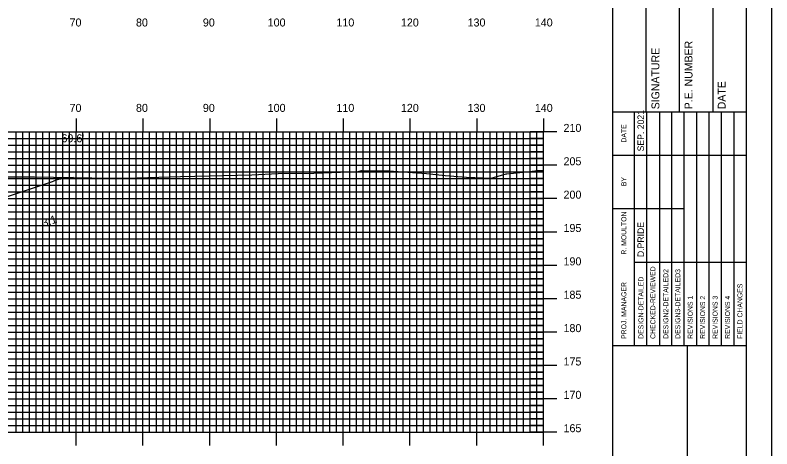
# Model space of a CAD drawing. Extents: x 1795633 to 1795976, y 442591 to 442811.
# Drawn here: x 1795859.7 to 1795973.1, y 442671.2 to 442736.2 of the extents above; entities that cross this region are included whole.
import ezdxf

# ---------------------------------------------------------------- set-up
doc = ezdxf.new("R2010")
doc.units = 0
for name, color, linetype in [('ANNOTATION', 7, 'Continuous'), ('BORDER', 7, 'Continuous'), ('D_Roadway_SlopeLines', 7, 'Continuous'), ('D_Text_Standard', 7, 'Continuous'), ('H_V ANNOTATION', 7, 'Continuous'), ('MAJOR', 7, 'Continuous'), ('MINOR', 7, 'Continuous'), ('PLOT BOUNDARY', 7, 'Continuous'), ('S_Roadway_Centerline', 7, 'Continuous')]:
    doc.layers.add(name, color=color, linetype=linetype)

msp = doc.modelspace()

# ---------------------------------------------------------------- linework, layer by layer
at = {"layer": 'BORDER'}
for p, q in [((1795949.28, 442596.67), (1795949.28, 442806.67)), ((1795954.28, 442721.67), (1795954.28, 442738.97)), ((1795959.28, 442721.67), (1795959.28, 442738.97)), ((1795964.28, 442721.67), (1795964.28, 442738.97)), ((1795949.28, 442721.67), (1795969.28, 442721.67)), ((1795949.28, 442686.67), (1795969.28, 442686.67)), ((1795960.46, 442616.67), (1795960.46, 442686.67))]:
    msp.add_line(p, q, dxfattribs=at)
msp.add_lwpolyline([(1795649.28, 442596.67), (1795969.28, 442596.67), (1795969.28, 442806.67), (1795649.28, 442806.67)], close=True, dxfattribs=at)
for points in [[(1795952.51, 442715.17), (1795952.51, 442721.67)], [(1795954.37, 442686.68), (1795954.37, 442721.67)], [(1795956.24, 442721.67), (1795956.24, 442686.68)], [(1795958.1, 442686.68), (1795958.1, 442721.67)], [(1795959.96, 442686.68), (1795959.96, 442721.67)], [(1795961.83, 442686.68), (1795961.83, 442721.67)], [(1795963.69, 442686.68), (1795963.69, 442721.67)], [(1795965.55, 442686.68), (1795965.55, 442721.67)], [(1795967.42, 442686.68), (1795967.42, 442721.67)], [(1795952.51, 442686.68), (1795952.51, 442720.26)], [(1795949.28, 442715.17), (1795969.28, 442715.17)], [(1795949.28, 442707.17), (1795952.51, 442707.17)], [(1795952.51, 442707.17), (1795959.96, 442707.17)], [(1795952.51, 442699.17), (1795969.28, 442699.17)]]:
    msp.add_lwpolyline(points, dxfattribs=at)
at = {"layer": 'D_Roadway_SlopeLines'}
msp.add_lwpolyline([(1795837.07, 442696.87), (1795838.97, 442704.47), (1795844.97, 442704.47), (1795865.49, 442711.3)], dxfattribs=at)
msp.add_arc((1795868.71, 442701.64), 10.19, 91.3738, 108.4349, dxfattribs=at)
at = {"layer": 'MAJOR'}
for p, q in [((1795868.88, 442720.67), (1795868.88, 442718.67)), ((1795878.88, 442720.67), (1795878.88, 442718.67)), ((1795888.88, 442720.67), (1795888.88, 442718.67)), ((1795898.88, 442720.67), (1795898.88, 442718.67)), ((1795908.88, 442720.67), (1795908.88, 442718.67)), ((1795918.88, 442720.67), (1795918.88, 442718.67)), ((1795928.88, 442720.67), (1795928.88, 442718.67)), ((1795938.88, 442720.67), (1795938.88, 442718.67)), ((1795658.88, 442718.67), (1795938.88, 442718.67)), ((1795658.88, 442718.67), (1795938.88, 442718.67)), ((1795868.88, 442673.67), (1795868.88, 442718.67)), ((1795878.88, 442673.67), (1795878.88, 442718.67)), ((1795888.88, 442673.67), (1795888.88, 442718.67)), ((1795898.88, 442673.67), (1795898.88, 442718.67)), ((1795908.88, 442673.67), (1795908.88, 442718.67)), ((1795918.88, 442673.67), (1795918.88, 442718.67)), ((1795928.88, 442673.67), (1795928.88, 442718.67)), ((1795940.88, 442718.67), (1795936.88, 442718.67)), ((1795938.88, 442673.67), (1795938.88, 442718.67)), ((1795938.88, 442673.67), (1795938.88, 442718.67)), ((1795658.88, 442713.67), (1795938.88, 442713.67)), ((1795940.88, 442713.67), (1795936.88, 442713.67)), ((1795658.88, 442708.67), (1795938.88, 442708.67)), ((1795940.88, 442708.67), (1795936.88, 442708.67)), ((1795658.88, 442703.67), (1795938.88, 442703.67)), ((1795940.88, 442703.67), (1795936.88, 442703.67)), ((1795658.88, 442698.67), (1795938.88, 442698.67)), ((1795940.88, 442698.67), (1795936.88, 442698.67)), ((1795658.88, 442693.67), (1795938.88, 442693.67)), ((1795940.88, 442693.67), (1795936.88, 442693.67)), ((1795658.88, 442688.67), (1795938.88, 442688.67)), ((1795940.88, 442688.67), (1795936.88, 442688.67)), ((1795658.88, 442683.67), (1795938.88, 442683.67)), ((1795940.88, 442683.67), (1795936.88, 442683.67)), ((1795658.88, 442678.67), (1795938.88, 442678.67)), ((1795940.88, 442678.67), (1795936.88, 442678.67)), ((1795658.88, 442673.67), (1795938.88, 442673.67)), ((1795658.88, 442673.67), (1795938.88, 442673.67)), ((1795868.88, 442671.66), (1795868.88, 442673.67)), ((1795878.88, 442671.66), (1795878.88, 442673.67)), ((1795888.88, 442671.66), (1795888.88, 442673.67)), ((1795898.88, 442671.66), (1795898.88, 442673.67)), ((1795908.88, 442671.66), (1795908.88, 442673.67)), ((1795918.88, 442671.66), (1795918.88, 442673.67)), ((1795928.88, 442671.66), (1795928.88, 442673.67)), ((1795940.88, 442673.67), (1795936.88, 442673.67)), ((1795938.88, 442671.66), (1795938.88, 442673.67))]:
    msp.add_line(p, q, dxfattribs=at)
at = {"layer": 'MINOR'}
for p, q in [((1795859.88, 442673.67), (1795859.88, 442718.67)), ((1795860.88, 442673.67), (1795860.88, 442718.67)), ((1795861.88, 442673.67), (1795861.88, 442718.67)), ((1795862.88, 442673.67), (1795862.88, 442718.67)), ((1795863.88, 442673.67), (1795863.88, 442718.67)), ((1795864.88, 442673.67), (1795864.88, 442718.67)), ((1795865.88, 442673.67), (1795865.88, 442718.67)), ((1795866.88, 442673.67), (1795866.88, 442718.67)), ((1795867.88, 442673.67), (1795867.88, 442718.67)), ((1795869.88, 442673.67), (1795869.88, 442718.67)), ((1795870.88, 442673.67), (1795870.88, 442718.67)), ((1795871.88, 442673.67), (1795871.88, 442718.67)), ((1795872.88, 442673.67), (1795872.88, 442718.67)), ((1795873.88, 442673.67), (1795873.88, 442718.67)), ((1795874.88, 442673.67), (1795874.88, 442718.67)), ((1795875.88, 442673.67), (1795875.88, 442718.67)), ((1795876.88, 442673.67), (1795876.88, 442718.67)), ((1795877.88, 442673.67), (1795877.88, 442718.67)), ((1795879.88, 442673.67), (1795879.88, 442718.67)), ((1795880.88, 442673.67), (1795880.88, 442718.67)), ((1795881.88, 442673.67), (1795881.88, 442718.67)), ((1795882.88, 442673.67), (1795882.88, 442718.67)), ((1795883.88, 442673.67), (1795883.88, 442718.67)), ((1795884.88, 442673.67), (1795884.88, 442718.67)), ((1795885.88, 442673.67), (1795885.88, 442718.67)), ((1795886.88, 442673.67), (1795886.88, 442718.67)), ((1795887.88, 442673.67), (1795887.88, 442718.67)), ((1795889.88, 442673.67), (1795889.88, 442718.67)), ((1795890.88, 442673.67), (1795890.88, 442718.67)), ((1795891.88, 442673.67), (1795891.88, 442718.67)), ((1795892.88, 442673.67), (1795892.88, 442718.67)), ((1795893.88, 442673.67), (1795893.88, 442718.67)), ((1795894.88, 442673.67), (1795894.88, 442718.67)), ((1795895.88, 442673.67), (1795895.88, 442718.67)), ((1795896.88, 442673.67), (1795896.88, 442718.67)), ((1795897.88, 442673.67), (1795897.88, 442718.67)), ((1795899.88, 442673.67), (1795899.88, 442718.67)), ((1795900.88, 442673.67), (1795900.88, 442718.67)), ((1795901.88, 442673.67), (1795901.88, 442718.67)), ((1795902.88, 442673.67), (1795902.88, 442718.67)), ((1795903.88, 442673.67), (1795903.88, 442718.67)), ((1795904.88, 442673.67), (1795904.88, 442718.67)), ((1795905.88, 442673.67), (1795905.88, 442718.67)), ((1795906.88, 442673.67), (1795906.88, 442718.67)), ((1795907.88, 442673.67), (1795907.88, 442718.67)), ((1795909.88, 442673.67), (1795909.88, 442718.67)), ((1795910.88, 442673.67), (1795910.88, 442718.67)), ((1795911.88, 442673.67), (1795911.88, 442718.67)), ((1795912.88, 442673.67), (1795912.88, 442718.67)), ((1795913.88, 442673.67), (1795913.88, 442718.67)), ((1795914.88, 442673.67), (1795914.88, 442718.67)), ((1795915.88, 442673.67), (1795915.88, 442718.67)), ((1795916.88, 442673.67), (1795916.88, 442718.67)), ((1795917.88, 442673.67), (1795917.88, 442718.67)), ((1795919.88, 442673.67), (1795919.88, 442718.67)), ((1795920.88, 442673.67), (1795920.88, 442718.67)), ((1795921.88, 442673.67), (1795921.88, 442718.67)), ((1795922.88, 442673.67), (1795922.88, 442718.67)), ((1795923.88, 442673.67), (1795923.88, 442718.67)), ((1795924.88, 442673.67), (1795924.88, 442718.67)), ((1795925.88, 442673.67), (1795925.88, 442718.67)), ((1795926.88, 442673.67), (1795926.88, 442718.67)), ((1795927.88, 442673.67), (1795927.88, 442718.67)), ((1795929.88, 442673.67), (1795929.88, 442718.67)), ((1795930.88, 442673.67), (1795930.88, 442718.67)), ((1795931.88, 442673.67), (1795931.88, 442718.67)), ((1795932.88, 442673.67), (1795932.88, 442718.67)), ((1795933.88, 442673.67), (1795933.88, 442718.67)), ((1795934.88, 442673.67), (1795934.88, 442718.67)), ((1795935.88, 442673.67), (1795935.88, 442718.67)), ((1795936.88, 442673.67), (1795936.88, 442718.67)), ((1795937.88, 442673.67), (1795937.88, 442718.67)), ((1795658.88, 442717.67), (1795938.88, 442717.67)), ((1795938.88, 442717.67), (1795936.88, 442717.67)), ((1795658.88, 442716.67), (1795938.88, 442716.67)), ((1795938.88, 442716.67), (1795936.88, 442716.67)), ((1795658.88, 442715.67), (1795938.88, 442715.67)), ((1795938.88, 442715.67), (1795936.88, 442715.67)), ((1795658.88, 442714.67), (1795938.88, 442714.67)), ((1795938.88, 442714.67), (1795936.88, 442714.67)), ((1795658.88, 442712.67), (1795938.88, 442712.67)), ((1795938.88, 442712.67), (1795936.88, 442712.67)), ((1795658.88, 442711.67), (1795938.88, 442711.67)), ((1795938.88, 442711.67), (1795936.88, 442711.67)), ((1795658.88, 442710.67), (1795938.88, 442710.67)), ((1795938.88, 442710.67), (1795936.88, 442710.67)), ((1795658.88, 442709.67), (1795938.88, 442709.67)), ((1795938.88, 442709.67), (1795936.88, 442709.67)), ((1795658.88, 442707.67), (1795938.88, 442707.67)), ((1795938.88, 442707.67), (1795936.88, 442707.67)), ((1795658.88, 442706.67), (1795938.88, 442706.67)), ((1795938.88, 442706.67), (1795936.88, 442706.67)), ((1795658.88, 442705.67), (1795938.88, 442705.67)), ((1795658.88, 442704.67), (1795938.88, 442704.67)), ((1795938.88, 442705.67), (1795936.88, 442705.67)), ((1795938.88, 442704.67), (1795936.88, 442704.67)), ((1795658.88, 442702.67), (1795938.88, 442702.67)), ((1795938.88, 442702.67), (1795936.88, 442702.67)), ((1795658.88, 442701.67), (1795938.88, 442701.67)), ((1795938.88, 442701.67), (1795936.88, 442701.67)), ((1795658.88, 442700.67), (1795938.88, 442700.67)), ((1795938.88, 442700.67), (1795936.88, 442700.67)), ((1795658.88, 442699.67), (1795938.88, 442699.67)), ((1795938.88, 442699.67), (1795936.88, 442699.67)), ((1795658.88, 442697.67), (1795938.88, 442697.67)), ((1795938.88, 442697.67), (1795936.88, 442697.67)), ((1795658.88, 442696.67), (1795938.88, 442696.67)), ((1795658.88, 442695.67), (1795938.88, 442695.67)), ((1795938.88, 442696.67), (1795936.88, 442696.67)), ((1795938.88, 442695.67), (1795936.88, 442695.67)), ((1795658.88, 442694.67), (1795938.88, 442694.67)), ((1795938.88, 442694.67), (1795936.88, 442694.67)), ((1795658.88, 442692.67), (1795938.88, 442692.67)), ((1795938.88, 442692.67), (1795936.88, 442692.67)), ((1795658.88, 442691.67), (1795938.88, 442691.67)), ((1795938.88, 442691.67), (1795936.88, 442691.67)), ((1795658.88, 442690.67), (1795938.88, 442690.67)), ((1795938.88, 442690.67), (1795936.88, 442690.67)), ((1795658.88, 442689.67), (1795938.88, 442689.67)), ((1795938.88, 442689.67), (1795936.88, 442689.67)), ((1795658.88, 442687.67), (1795938.88, 442687.67)), ((1795938.88, 442687.67), (1795936.88, 442687.67)), ((1795658.88, 442686.67), (1795938.88, 442686.67)), ((1795938.88, 442686.67), (1795936.88, 442686.67)), ((1795658.88, 442685.67), (1795938.88, 442685.67)), ((1795938.88, 442685.67), (1795936.88, 442685.67)), ((1795658.88, 442684.67), (1795938.88, 442684.67)), ((1795938.88, 442684.67), (1795936.88, 442684.67)), ((1795658.88, 442682.67), (1795938.88, 442682.67)), ((1795938.88, 442682.67), (1795936.88, 442682.67)), ((1795658.88, 442681.67), (1795938.88, 442681.67)), ((1795938.88, 442681.67), (1795936.88, 442681.67)), ((1795658.88, 442680.67), (1795938.88, 442680.67)), ((1795938.88, 442680.67), (1795936.88, 442680.67)), ((1795658.88, 442679.67), (1795938.88, 442679.67)), ((1795938.88, 442679.67), (1795936.88, 442679.67)), ((1795658.88, 442677.67), (1795938.88, 442677.67)), ((1795938.88, 442677.67), (1795936.88, 442677.67)), ((1795658.88, 442676.67), (1795938.88, 442676.67)), ((1795938.88, 442676.67), (1795936.88, 442676.67)), ((1795658.88, 442675.67), (1795938.88, 442675.67)), ((1795938.88, 442675.67), (1795936.88, 442675.67)), ((1795658.88, 442674.67), (1795938.88, 442674.67)), ((1795938.88, 442674.67), (1795936.88, 442674.67))]:
    msp.add_line(p, q, dxfattribs=at)
at = {"layer": 'PLOT BOUNDARY'}
msp.add_lwpolyline([(1795633.09, 442590.55), (1795973.09, 442590.55), (1795973.09, 442810.55), (1795633.09, 442810.55)], close=True, dxfattribs=at)
at = {"layer": 'S_Roadway_Centerline'}
msp.add_lwpolyline([(1795857.18, 442711.94), (1795862.64, 442711.93), (1795871.2, 442711.77), (1795874.75, 442711.73), (1795876.34, 442711.74), (1795884.48, 442711.97), (1795895.18, 442712.26), (1795899.13, 442712.46), (1795904.49, 442712.47), (1795911.12, 442712.74), (1795911.6, 442712.89), (1795915.69, 442712.83), (1795921.35, 442712.43), (1795924.16, 442712.12), (1795927.35, 442711.9), (1795931.06, 442711.76), (1795933.3, 442712.38), (1795933.37, 442712.39), (1795936.84, 442712.75), (1795937.93, 442712.87), (1795938.88, 442712.93)], dxfattribs=at)

# ---------------------------------------------------------------- texts
at = {"layer": 'ANNOTATION'}
msp.add_text('3:1', height=1.2, rotation=18.7155, dxfattribs=at).set_placement((1795863.98, 442704.4))
msp.add_text('3:1', height=1.2, rotation=18.7155, dxfattribs=at).set_placement((1795863.98, 442704.4))
at = {"layer": 'BORDER'}
for s, height, p in [('P.E. NUMBER', 1.1811, (1795961.2, 442722.06)), ('SIGNATURE', 1.181, (1795956.24, 442722.06)), ('DATE', 1.181, (1795966.16, 442722.06)), ('SEP. 2021', 0.969, (1795953.93, 442715.76)), ('DATE', 0.743, (1795951.29, 442717.08)), ('BY', 0.743, (1795951.29, 442710.54)), ('R. MOULTON', 0.745, (1795951.29, 442700.28)), ('D.PRIDE', 0.969, (1795953.93, 442699.92)), ('CHECKED-REVIEWED', 0.7455, (1795955.64, 442687.65)), ('DESIGN2-DETAILED2', 0.7455, (1795957.58, 442687.65)), ('DESIGN3-DETAILED3', 0.7455, (1795959.37, 442687.65)), ('PROJ. MANAGER', 0.7455, (1795951.29, 442687.65)), ('DESIGN-DETAILED', 0.7455, (1795953.85, 442687.65)), ('FIELD CHANGES', 0.7455, (1795968.68, 442687.65)), ('REVISIONS 1', 0.7455, (1795961.23, 442687.65)), ('REVISIONS 2', 0.7455, (1795963.09, 442687.65)), ('REVISIONS 3', 0.7455, (1795964.96, 442687.65)), ('REVISIONS 4', 0.7455, (1795966.82, 442687.65))]:
    msp.add_text(s, height=height, rotation=90, dxfattribs=at).set_placement(p)
at = {"layer": 'D_Text_Standard'}
msp.add_text("69.6'", height=1.2, dxfattribs=at).set_placement((1795866.67, 442717.12))
at = {"layer": 'H_V ANNOTATION'}
for s, p in [('70', (1795867.88, 442734.47)), ('80', (1795877.83, 442734.47)), ('90', (1795887.85, 442734.47)), ('100', (1795897.56, 442734.47)), ('110', (1795907.86, 442734.47)), ('120', (1795917.52, 442734.47)), ('130', (1795927.51, 442734.47)), ('140', (1795937.58, 442734.47)), ('70', (1795867.88, 442721.67)), ('80', (1795877.83, 442721.67)), ('90', (1795887.85, 442721.67)), ('100', (1795897.56, 442721.67)), ('110', (1795907.86, 442721.67)), ('120', (1795917.52, 442721.67)), ('130', (1795927.51, 442721.67)), ('140', (1795937.58, 442721.67)), ('210', (1795941.88, 442718.67)), ('205', (1795941.88, 442713.67)), ('200', (1795941.88, 442708.67)), ('195', (1795941.88, 442703.67)), ('190', (1795941.88, 442698.67)), ('185', (1795941.88, 442693.67)), ('180', (1795941.88, 442688.67)), ('175', (1795941.88, 442683.67)), ('170', (1795941.88, 442678.67)), ('165', (1795941.88, 442673.67))]:
    msp.add_text(s, height=1.2, dxfattribs=at).set_placement(p)

doc.saveas('drawing.dxf')
